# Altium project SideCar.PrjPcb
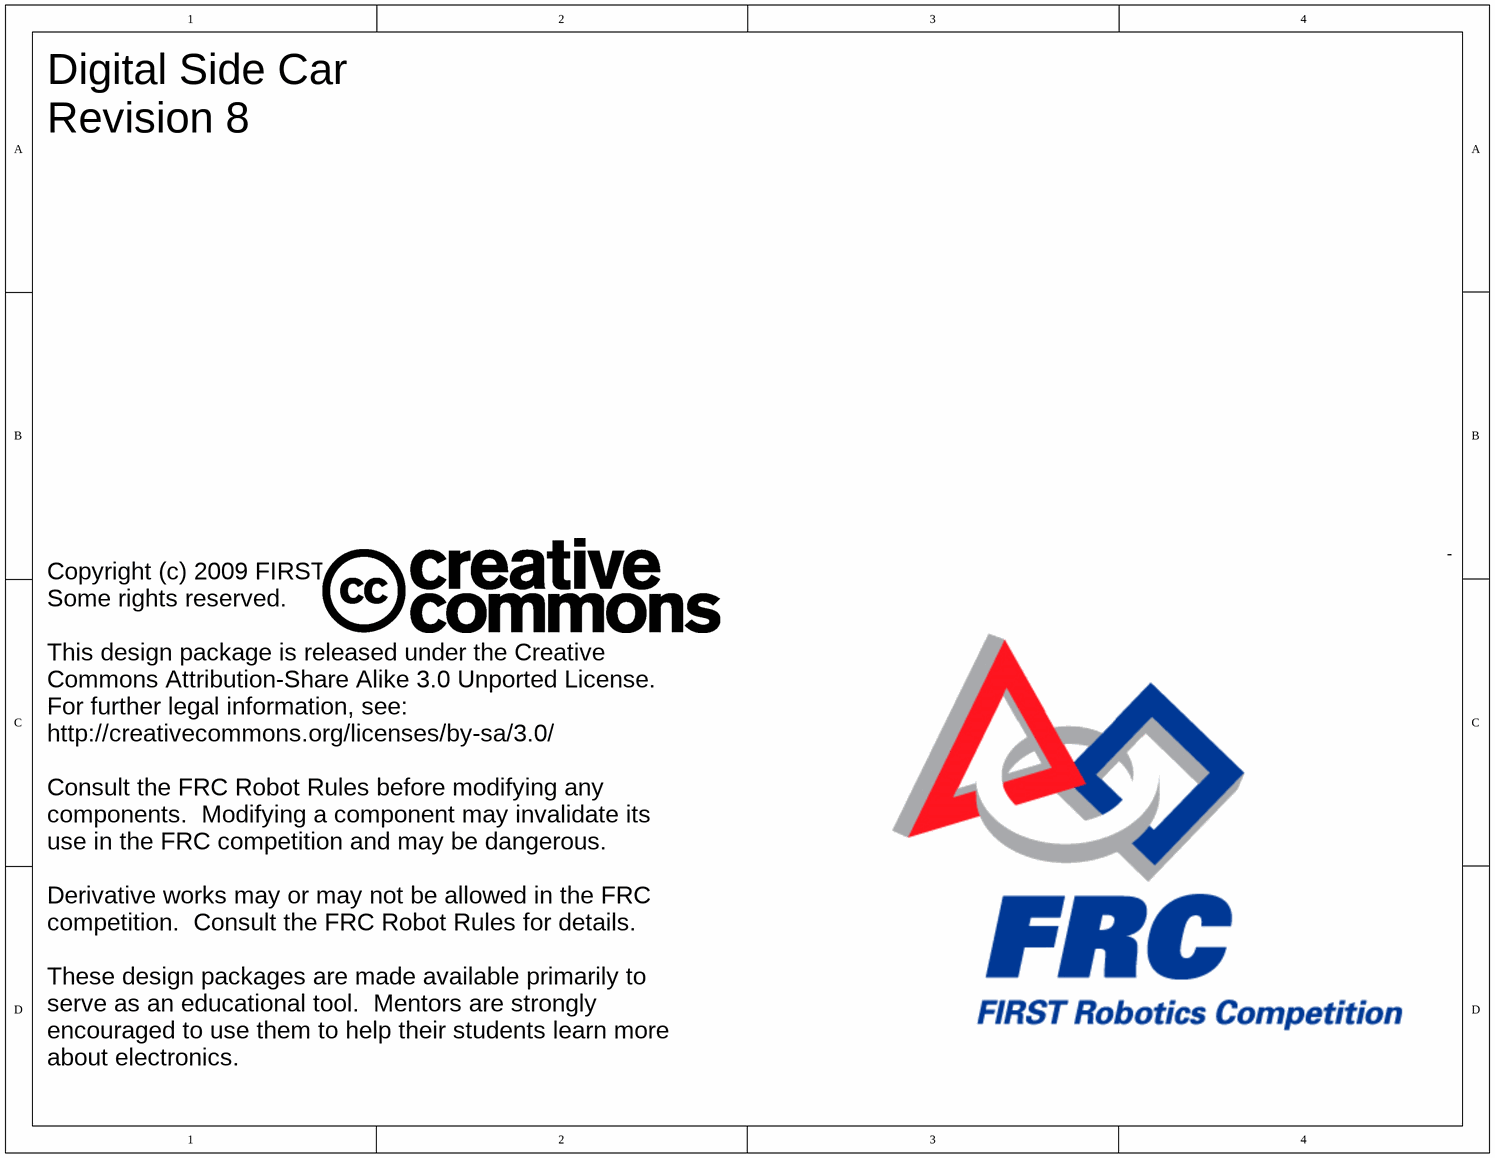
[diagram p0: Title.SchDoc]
ProjectTitle: Digital Side Car, Rev 8
5 sheets, 116 parts. Net scope: global (net labels, ports and power ports of the same name join across sheets).
Board file: SideCar.PcbDoc
Sheets:
  Title.SchDoc
  cRIO Connectors.SchDoc
  PWM Outputs.SchDoc
  Power.SchDoc
  Relay Outputs.SchDoc

## Sheet Title.SchDoc
size Letter; SheetNumber: 1

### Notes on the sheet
- Digital Side Car
  Revision 8
- Copyright (c) 2009 FIRST
  Some rights reserved.
  This design package is released under the Creative Commons Attribution-Share Alike 3.0 Unported License.  For further legal information, see:
  http://creativecommons.org/licenses/by-sa/3.0/
  Consult the FRC Robot Rules before modifying any components.  Modifying a component may invalidate its use in the FRC competition and may be dangerous.
  Derivative works may or may not be allowed in the FRC competition.  Consult the FRC Robot Rules for details.
  These design packages are made available primarily to serve as an educational tool.  Mentors are strongly encouraged to use them to help their students learn more about electronics.

## Sheet cRIO Connectors.SchDoc: cRIO Connectors
size Letter; DrawnBy: RHB; DocumentNumber: 1; Revision: 2; SheetNumber: 1; SheetTotal: 4
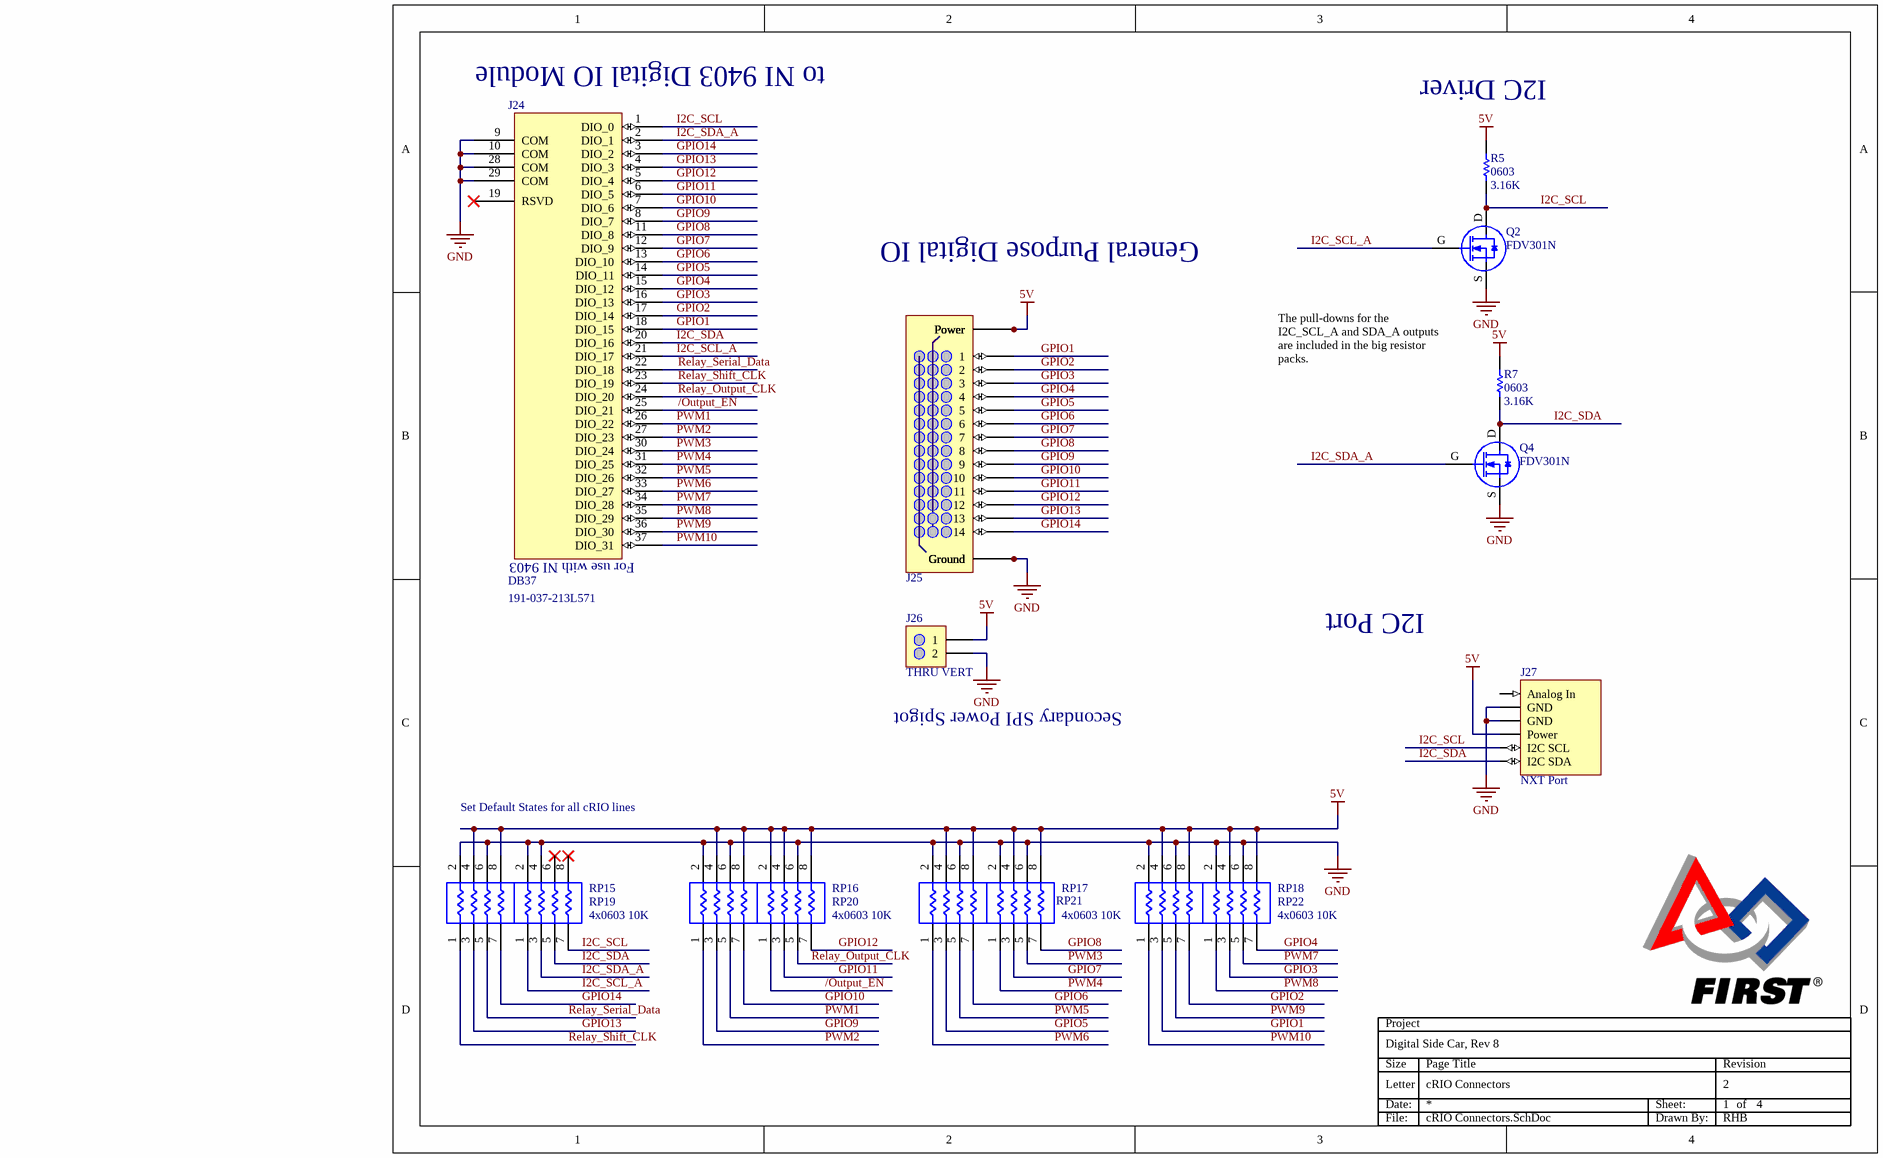
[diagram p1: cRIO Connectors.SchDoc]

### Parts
J24  DB37  MFG_PN: 191-037-213L571  [DB37- THRU]
J25  3x12 Bird Pins  [H100P3x14 TSW-114-07-T-T]  (value not drawn)
J26  THRU VERT  [H100P2]
J27  NXT Port  [NXT RJ]
Q2  FDV301N  [SOT-23 FET]
Q4  FDV301N  [SOT-23 FET]
R5  value 3.16K  Footprint: 0603  [R0603_C]  (hidden comment: 3.16k ohm 0603 1%)
R7  value 3.16K  Footprint: 0603  [R0603_C]  (hidden comment: 3.16k ohm 0603 1%)
RP15  4x0603 10K  [R0603x4 - Convex]
RP16  4x0603 10K  [R0603x4 - Convex]
RP17  4x0603 10K  [R0603x4 - Convex]
RP18  4x0603 10K  [R0603x4 - Convex]
RP19  4x0603 10K  [R0603x4 - Convex]  (value not drawn)
RP20  4x0603 10K  [R0603x4 - Convex]  (value not drawn)
RP21  4x0603 10K  [R0603x4 - Convex]  (value not drawn)
RP22  4x0603 10K  [R0603x4 - Convex]  (value not drawn)

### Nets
5V: J25.2(Power) J25.5(Power) J25.8(Power) J25.11(Power) J25.14(Power) J25.17(Power) J25.20(Power) J25.23(Power) J25.26(Power) J25.29(Power) J25.32(Power) J25.35(Power) J25.38(Power) J25.41(Power) J26.1 J27.4(Power) R5.2 R7.2 RP15.4 RP15.8 RP16.4 RP16.8 RP17.4 RP17.8 RP18.4 RP18.8 RP20.2 RP20.4 RP20.8 RP21.4 RP21.8 RP22.4 RP22.8
GND: J24.9(COM) J24.10(COM) J24.28(COM) J24.29(COM) J25.3(Ground) J25.6(Ground) J25.9(Ground) J25.12(Ground) J25.15(Ground) J25.18(Ground) J25.21(Ground) J25.24(Ground) J25.27(Ground) J25.30(Ground) J25.33(Ground) J25.36(Ground) J25.39(Ground) J25.42(Ground) J26.2 J27.2(GND) J27.3(GND) Q2.S Q4.S RP15.2 RP15.6 RP16.2 RP16.6 RP17.2 RP17.6 RP18.2 RP18.6 RP19.2 RP19.4 RP20.6 RP21.2 RP21.6 RP22.2 RP22.6
/Output_EN: J24.25(DIO_21) RP20.1
GPIO1: J24.18(DIO_15) J25.1 RP18.3
GPIO2: J24.17(DIO_14) J25.4(2) RP18.7
GPIO3: J24.16(DIO_13) J25.7(3) RP22.3
GPIO4: J24.15(DIO_12) J25.10(4) RP22.7
GPIO5: J24.14(DIO_11) J25.13(5) RP17.3
GPIO6: J24.13(DIO_10) J25.16(6) RP17.7
GPIO7: J24.12(DIO_9) J25.19(7) RP21.3
GPIO8: J24.11(DIO_8) J25.22(8) RP21.7
GPIO9: J24.8(DIO_7) J25.25(9) RP16.3
GPIO10: J24.7(DIO_6) J25.28(10) RP16.7
GPIO11: J24.6(DIO_5) J25.31(11) RP20.3
GPIO12: J24.5(DIO_4) J25.34(12) RP20.7
GPIO13: J24.4(DIO_3) J25.37(13) RP15.3
GPIO14: J24.3(DIO_2) J25.40(14) RP15.7
I2C_SCL: J24.1(DIO_0) J27.5(I2C_SCL) Q2.D R5.1 RP19.7
I2C_SCL_A: J24.21(DIO_17) Q2.G RP19.1
I2C_SDA: J24.20(DIO_16) J27.6(I2C_SDA) Q4.D R7.1 RP19.5
I2C_SDA_A: J24.2(DIO_1) Q4.G RP19.3
PWM1: J24.26(DIO_22) RP16.5
PWM2: J24.27(DIO_23) RP16.1
PWM3: J24.30(DIO_24) RP21.5
PWM4: J24.31(DIO_25) RP21.1
PWM5: J24.32(DIO_26) RP17.5
PWM6: J24.33(DIO_27) RP17.1
PWM7: J24.34(DIO_28) RP22.5
PWM8: J24.35(DIO_29) RP22.1
PWM9: J24.36(DIO_30) RP18.5
PWM10: J24.37(DIO_31) RP18.1
Relay_Output_CLK: J24.24(DIO_20) RP20.5
Relay_Serial_Data: J24.22(DIO_18) RP15.5
Relay_Shift_CLK: J24.23(DIO_19) RP15.1

Not connected (* = marked no-connect by the designer): J24 19(RSVD)*; J27 1(Analog_In); RP19 6* 8*

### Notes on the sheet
- (near J24) to NI 9403 Digital IO Module
- (near R5) I2C Driver
- General Purpose Digital IO
- The pull-downs for the I2C_SCL_A and SDA_A outputs are included in the big resistor packs.
- I2C Port
- Secondary SPI Power Spigot
- Set Default States for all cRIO lines

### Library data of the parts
J24 = Norcomp 191-037-213L571: D-SUB RCPT STR 37POS PCB AU; DIST: DigiKey; DIST_PN: 191-037-213L571-ND; MFG: Norcomp Inc.; Cost (MOQ): 3.00900
J25 = H100 3x14 THRU VERT: 3x14 Bird Pins; DIST: Samtec; DIST_PN: TSW-114-07-T-T
J26 = H100 1x2 THRU VERT: 1x2 Bird Pins; DIST: Samtec; DIST_PN: TSW-102-07-T-S; BOM Note: Generic
J27 = NXT RJ12 Connector
Q2 Q4 = FDV301N: N-Ch Logic FET, 25V, 0.22A, 5 Ohm; MFG: Fairchild; DIST: DigiKey; DIST_PN: FDV301NCT-ND; R_DS: 4000; V_DS: 25; V_GS: 8; R?JC: 357; Topology: N; Cost (1000): 0.05720; Cost (MOQ): 026000; Q_G (nC): 0.49; V_THRESH (Volts): 0.65 - 0.85 - 1.5; ID @ TA = 25°C (Amps): 0.22
R5 R7 = 3.16k ohm 0603 1%: MFG: Rohm; MFG_PN: MCR03EZPFX3161; DIST: DigiKey; DIST_PN: RHM3.16KHCT-ND; Power: 0.1 W
RP15-RP18 = 10k 5% 4x0603 Isolated: 10K 5% Isolated Resistor Network; MFG: Yageo; MFG_PN: YC164-JR-0710KL; DIST: DigiKey; DIST_PN: YC164J-10KCT-ND; Number of Resistors: 4; Power: 62.5mW; Cost (1000): 0.00630; Cost (MOQ): 0.01100
RP19-RP22 = 10K 5% 4x0603 Isolated: 10K 5% Isolated Resistor Network; MFG: Yageo; MFG_PN: YC164-JR-0710KL; DIST: DigiKey; DIST_PN: YC164J-10KCT-ND; Number of Resistors: 4; Power: 62.5mW; Cost (1000): 0.00630; Cost (MOQ): 0.01100

## Sheet PWM Outputs.SchDoc: PWM Outputs
size Letter; DrawnBy: RHB; DocumentNumber: 3; Revision: 4; SheetNumber: 2; SheetTotal: 4
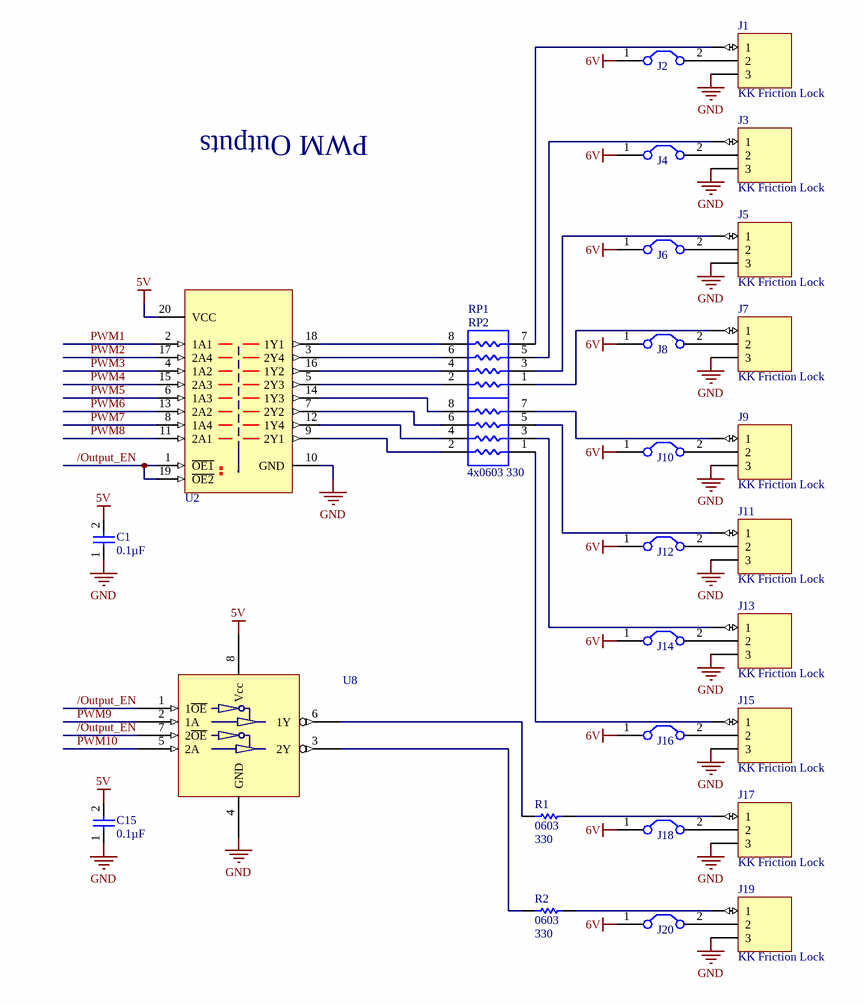
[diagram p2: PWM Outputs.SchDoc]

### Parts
(Parts that share a designator on the sheet are numbered #1, #2 ... from top to bottom, then left to right.)
C1  value 0.1µF  [C0805_C]  (hidden comment: 0.1uF 0805 Bypass)
C15  value 0.1µF  [C0805_C]  (hidden comment: 0.1uF 0805 Bypass)
J1  KK Friction Lock  [KK100P3]
J2  Jumper  [H100P2]  (value not drawn)
J3  KK Friction Lock  [KK100P3]
J4  Jumper  [H100P2]  (value not drawn)
J5  KK Friction Lock  [KK100P3]
J6  Jumper  [H100P2]  (value not drawn)
J7  KK Friction Lock  [KK100P3]
J8  Jumper  [H100P2]  (value not drawn)
J9  KK Friction Lock  [KK100P3]
J10  Jumper  [H100P2]  (value not drawn)
J11  KK Friction Lock  [KK100P3]
J12  Jumper  [H100P2]  (value not drawn)
J13  KK Friction Lock  [KK100P3]
J14  Jumper  [H100P2]  (value not drawn)
J15  KK Friction Lock  [KK100P3]
J16  Jumper  [H100P2]  (value not drawn)
J17  KK Friction Lock  [KK100P3]
J18  Jumper  [H100P2]  (value not drawn)
J19  KK Friction Lock  [KK100P3]
J20  Jumper  [H100P2]  (value not drawn)
R1  value 330  Footprint: 0603  [R0603_C]  (hidden comment: 470 ohm 0603 1%)
R2  value 330  Footprint: 0603  [R0603_C]  (hidden comment: 470 ohm 0603 1%)
RP1  4x0603 330  [R0603x4 - Convex]
RP2  4x0603 330  [R0603x4 - Convex]  (value not drawn)
U2#1  SN74AC244DWR  [DW020_N]  (value not drawn)
U8  Dual Buffer  [TSOP65P400X130-8N]  (value not drawn)

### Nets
5V: C1.2 C15.2 U2#1.20(VCC) U8.8(Vcc)
6V: J2.1 J4.1 J6.1 J8.1 J10.1 J12.1 J14.1 J16.1 J18.1 J20.1
GND: C1.1 C15.1 J1.3 J3.3 J5.3 J7.3 J9.3 J11.3 J13.3 J15.3 J17.3 J19.3 U2#1.10(GND) U8.4(GND)
/Output_EN: U2#1.1(~{OE1}) U2#1.19(~{OE2}) U8.1(1~{OE}) U8.7(2~{OE})
PWM1: U2#1.2(1A1)
PWM2: U2#1.17(2A4)
PWM3: U2#1.4(1A2)
PWM4: U2#1.15(2A3)
PWM5: U2#1.6(1A3)
PWM6: U2#1.13(2A2)
PWM7: U2#1.8(1A4)
PWM8: U2#1.11(2A1)
PWM9: U8.2(1A)
PWM10: U8.5(2A)
NetJ1_1: J1.1 RP2.7
NetJ1_2: J1.2 J2.2
NetJ3_1: J3.1 RP2.5
NetJ3_2: J3.2 J4.2
NetJ5_1: J5.1 RP2.3
NetJ5_2: J5.2 J6.2
NetJ7_1: J7.1 RP2.1
NetJ7_2: J7.2 J8.2
NetJ9_1: J9.1 RP1.7
NetJ9_2: J9.2 J10.2
NetJ11_1: J11.1 RP1.5
NetJ11_2: J11.2 J12.2
NetJ13_1: J13.1 RP1.3
NetJ13_2: J13.2 J14.2
NetJ15_1: J15.1 RP1.1
NetJ15_2: J15.2 J16.2
NetJ17_1: J17.1 R1.1
NetJ17_2: J17.2 J18.2
NetJ19_1: J19.1 R2.1
NetJ19_2: J19.2 J20.2
NetR1_2: R1.2 U8.6(1Y)
NetR2_2: R2.2 U8.3(2Y)
NetRP1_2: RP1.2 U2#1.9(2Y1)
NetRP1_4: RP1.4 U2#1.12(1Y4)
NetRP1_6: RP1.6 U2#1.7(2Y2)
NetRP1_8: RP1.8 U2#1.14(1Y3)
NetRP2_2: RP2.2 U2#1.5(2Y3)
NetRP2_4: RP2.4 U2#1.16(1Y2)
NetRP2_6: RP2.6 U2#1.3(2Y4)
NetRP2_8: RP2.8 U2#1.18(1Y1)

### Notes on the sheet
- PWM Outputs

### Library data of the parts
C1 C15 = 0.1uF 0805 Bypass: Capacitor; MFG: Kemet; MFG_PN: C0805C104K5RACTU; DIST: DigiKey; DIST_PN: 399-1170-1-ND; Tolerance: ±10%; Temperature Coefficient: X7R; Voltage: 50 V
J1 J3 J5 J7 J9 J11 J13 J15 J17 J19 = KK100P3: DIST: DigiKey; DIST_PN: WM4201-ND; MFG: Molex/Waldom Electronics Corp; Checked: SCH 11/11/07
J2 J4 J6 J8 J10 J12 J14 J16 J18 J20 = Jumper 100mil: DIST: DigiKey; DIST_PN: WM4000-ND; MFG: Molex/Waldom Electronics Corp; Checked: SCH 11/17/07
R1 R2 = 330 ohm 0603 1%: MFG: Rohm; MFG_PN: MCR03EZPFX3300; DIST: DigiKey; DIST_PN: RHM330HCT-ND; Power: 0.1; Cost (1000): 0.01595; Cost (MOQ): 0.076; BOM Note: Generic - May be replaced by equal or better part
RP1 RP2 = 330 5% 4x0603 Isolated: 330 5% Isolated Resistor Network; MFG: Yageo; MFG_PN: YC164-JR-07330RL; DIST: DigiKey; DIST_PN: YC164J-330CT-ND; Number of Resistors: 4; Power: 62.5mW; Value: 330; Cost (1000): 0.00630; Cost (MOQ): 0.01100
U2#1 = SN74AC244DWR: 8x Line Driver, Non-Inverting; MFG: TI; DIST: DigiKey; DIST_PN: 296-1057-1-ND; Cost (1000): 0.18260; Cost (MOQ): 0.55000
U8 = SN74LVC2G125DCTR Dual Buffer: MFG: TI; DIST: DigiKey; DIST_PN: 296-12164-1-ND; Output Current: 32mA @ Vcc 4.5; Operating Voltage: 1.65 to 5.5 V; Cost (1000): 0.15960; Cost (MOQ): 0.48000

## Sheet Power.SchDoc: Power Input, Supplies & Indicators
size Letter; DrawnBy: EJVW; Revision: 4; SheetNumber: 3; SheetTotal: 4
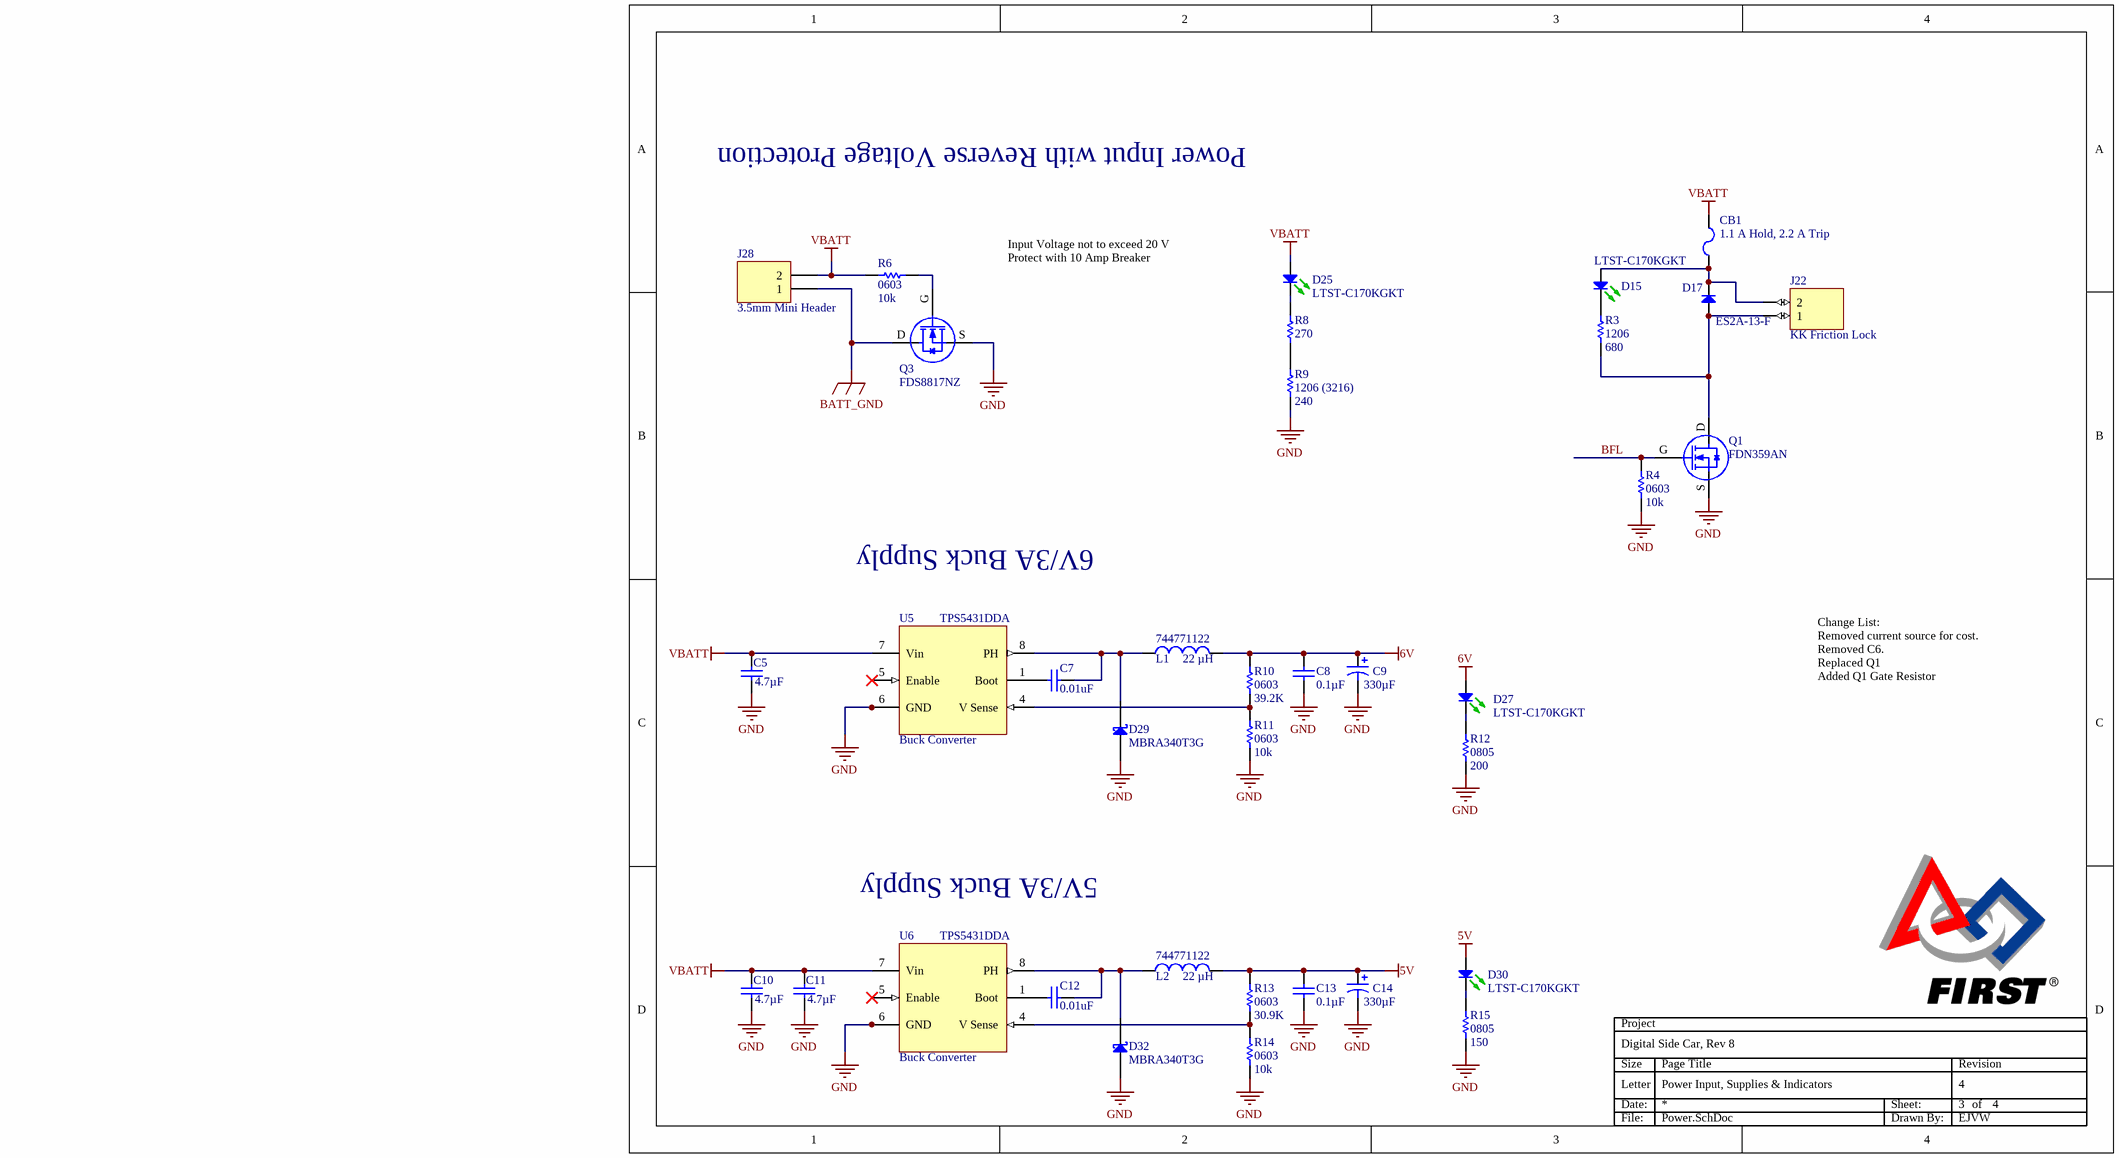
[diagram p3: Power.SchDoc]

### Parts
C5  value 4.7µF  [C0805_C]  (hidden comment: 4.7UF 0805 25V X5R)
C7  value 0.01uF  [C0603_C]  (hidden comment: 0.01uF 0603)
C8  value 0.1µF  [C0805_C]  (hidden comment: 0.1uF 0805 Bypass)
C9  value 330µF  [SMT-CAN Nippon F80]  (hidden comment: 330µF SMT - Chemi-Con)
C10  value 4.7µF  [C0805_C]  (hidden comment: 4.7UF 0805 25V X5R)
C11  value 4.7µF  [C0805_C]  (hidden comment: 4.7UF 0805 25V X5R)
C12  value 0.01uF  [C0603_C]  (hidden comment: 0.01uF 0603)
C13  value 0.1µF  [C0805_C]  (hidden comment: 0.1uF 0805 Bypass)
C14  value 330µF  [SMT-CAN Nippon F80]  (hidden comment: 330µF SMT - Chemi-Con)
CB1  1.1 A Hold, 2.2 A Trip  [PTC1812]
D15  LTST-C170KGKT  [LED_0805 1.1 Green]
D17  25ns 2A Standard Rectifier  [SMB]  (value not drawn)
D25  LTST-C170KGKT  [LED_0805 1.1 Green]
D27  LTST-C170KGKT  [LED_0805 1.1 Green]
D29  MBRA340T3G  [SMA]
D30  LTST-C170KGKT  [LED_0805 1.1 Green]
D32  MBRA340T3G  [SMA]
J22  KK Friction Lock  [KK100P2]
J28  3.5mm Mini Header  [WAGO 734-132]
L1  value 22 µH  MFG_PN: 744771122  [Wurth WE-PD L]  (hidden comment: 22 µH 3.37 A)
L2  value 22 µH  MFG_PN: 744771122  [Wurth WE-PD L]  (hidden comment: 22 µH 3.37 A)
Q1  FDN359AN  [SOT-23 FET]
Q3  FDS8817NZ  [SO-8_M FET]
R3  value 680  Footprint: 1206  [R1206_C]  (hidden comment: 680 ohm 1206 5%)
R4  value 10k  Footprint: 0603  [R0603_C]  (hidden comment: 10k ohm 0603 1%)
R6  value 10k  Footprint: 0603  [R0603_C]  (hidden comment: 10k ohm 0603 1%)
R8  value 270  [R1206_C]  (hidden comment: 270 ohm 1206 5%)
R9  value 240  Footprint: 1206 (3216)  [R1206_C]  (hidden comment: 240 ohm 1206 5%)
R10  value 39.2K  Footprint: 0603  [R0603_C]  (hidden comment: 2.55k ohm 0603 1%)
R11  value 10k  Footprint: 0603  [R0603_C]  (hidden comment: 10k ohm 0603 1%)
R12  value 200  Footprint: 0805  [R0805_M]  (hidden comment: 200 ohm 0805 1%)
R13  value 30.9K  Footprint: 0603  [R0603_C]  (hidden comment: 30.9k ohm 0603 1%)
R14  value 10k  Footprint: 0603  [R0603_C]  (hidden comment: 10k ohm 0603 1%)
R15  value 150  Footprint: 0805  [R0805_M]  (hidden comment: 150 ohm 0805 1%)
U5  Buck Converter  MFG_PN: TPS5431DDA  [TPS543X]
U6  Buck Converter  MFG_PN: TPS5431DDA  [TPS543X]

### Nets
5V: C13.2 C14.+ D30.A L2.2 R13.2
6V: C8.2 C9.+ D27.A L1.2 R10.2
BATT_GND: J28.1 Q3.D
GND: C5.1 C8.1 C9.- C10.1 C11.1 C13.1 C14.- D29.A D32.A Q1.S Q3.S R4.1 R9.1 R11.1 R12.1 R14.1 R15.1 U5.6(GND) U5.PAD U6.6(GND) U6.PAD
VBATT: C5.2 C10.2 C11.2 CB1.2 D25.A J28.2 R6.2 U5.7(Vin) U6.7(Vin)
BFL: Q1.G R4.2
NetC7_1: C7.1 U5.1(Boot)
NetC7_2: C7.2 D29.K L1.1 U5.8(PH)
NetC12_1: C12.1 U6.1(Boot)
NetC12_2: C12.2 D32.K L2.1 U6.8(PH)
NetCB1_1: CB1.1 D15.A D17.K J22.2
NetD15_K: D15.K R3.2
NetD17_A: D17.A J22.1 Q1.D R3.1
NetD25_K: D25.K R8.2
NetD27_K: D27.K R12.2
NetD30_K: D30.K R15.2
NetQ3_G: Q3.G R6.1
NetR8_1: R8.1 R9.2
NetR10_1: R10.1 R11.2 U5.4(V_Sense)
NetR13_1: R13.1 R14.2 U6.4(V_Sense)

Not connected (* = marked no-connect by the designer): U5 5(Enable)*; U6 5(Enable)*

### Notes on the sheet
- Power Input with Reverse Voltage Protection
- Input Voltage not to exceed 20 V
  Protect with 10 Amp Breaker
- 6V/3A Buck Supply
- Change List:
  Removed current source for cost.
  Removed C6.
  Replaced Q1
  Added Q1 Gate Resistor
- 5V/3A Buck Supply

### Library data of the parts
C5 C10 C11 = 4.7uF 0805 25V X5R: CERAMIC 4.7uF 25V X5R 0805; MFG: Panasonic - ECG; MFG_PN: ECJ-2FB1E475M; DIST: DigiKey; DIST_PN: PCC2321CT-ND; Tolerance: ±20%; Cost (1000): 0.08988
C7 C12 = 0.01 uF 0603 50V: MFG: Kemet; MFG_PN: C0603C103K5RACTU; DIST: DigiKey; DIST_PN: 399-1091-1-ND; Tolerance: ±10%; Temperature Coefficient: X7R; Voltage: 50V
C8 C13 = 0.1uF 0805 Bypass: Capacitor; MFG: Kemet; MFG_PN: C0805C104K5RACTU; DIST: DigiKey; DIST_PN: 399-1170-1-ND; Tolerance: ±10%; Temperature Coefficient: X7R; Voltage: 50 V; Cost (1000): 0.01260
C9 C14 = 330µF 6.3V CAN-SMT: 330µF 6.3V ELECT CAN-SMT; DIST: DigiKey; DIST_PN: 565-2059-1-ND; MFG: United Chemi-Con; MFG_PN: EMVA6R3ADA331MF80G; Tolerance: ±20%; Max Temperature: 85 C; Ripple Current: 0.135 A; Cost (1000): 0.10266
CB1 = MF-MSMF110/16-2: PTC 1.1A /  2.2A SMT; MFG: Bourns Inc.; DIST: DigiKey; DIST_PN: MF-MSMF110/16-2CT-ND; R_min: 0.04; R_max: 0.21; Time to Trip: 0.3 s @ 8 A; V Max: 16V; I trip (A): 2.2; I max (A): 100A; Cost (1000): 0.42300; Cost (MOQ): 0.63000
D15 = LTST-C170KGKT: Green 0805 20mA 2.0V 35mCd; MFG: LITE-ON INC; DIST: DigiKey; DIST_PN: 160-1414-1-ND; I_F: 20; Luminous Intensity: 35; Maximum Continuous Current: 30; V_F: 2.0; Cost (1000): 0.05800; Cost (MOQ): 0.12000
D17 = ES2A-13-F: MFG: Diodes Inc; DIST: DIGIKEY; DIST_PN: ES2A-FDICT-ND; Voltage Rating: 50 V; Surge Rating (8.3ms Half Sine): 50 A; Forward Voltage: 0.92 V
D25 D27 D30 = LTST-C170KGKT: Green 0805 20mA 2.0V 35mCd; DIST: DigiKey; DIST_PN: 160-1414-1-ND; MFG: LITE-ON INC; V_F: 2.0; I_F: 20; Maximum Continuous Current: 30; Luminous Intensity: 35; Cost (1000): 0.05800; Cost (MOQ): 0.12000
D29 D32 = MBRA340T3G: 3A Schottky Diode; DIST: DigiKey; DIST_PN: MBRA340T3GOSCT-ND; MFG: ON Semiconductor; Forward Voltage: 0.38; Surge Rating (8.3ms Half Sine): 100A; Voltage Rating: 40V
J22 = KK100P2: DIST: DigiKey; DIST_PN: WM4200-ND; MFG: Molex/Waldom Electronics Corp; Checked: SCH 11/11/07
J28 = WAGO 734-132: 3.5mm Header Protected against Mismating; MFG: WAGO; Current Rating: 10 A; Mates With: 734-102/037-000
L1 L2 = WE-PD-L 22: 22 µH 3.37 A 20% SMD; MFG: Wurth; DIST: Digikey; DIST_PN: 732-1211-2-ND; DCR (Ohms): .0648; Cost (1000): 1.02000; Cost (MOQ): 3.06000; IRMS (40C) A: 3.37; ISAT (10%)  A: 3.77; SRF (MHz): 13
Q1 = FDN359AN: N-Channel Powertrench MOSFET, 30V, 2.7A, 2.5mOhm; MFG: Fairchild; DIST: DigiKey; DIST_PN: FDN359ANCT-ND; R_DS: 46 mOhms; V_GS: 20V; I_D Continuous: 2.7; Checked: SCH 11/17/07; R?JC: 250 C/W; Topology: N; Cost (1000): 0.19551; Cost (MOQ): 0.59000; Q_G (nC): 5; V_THRESH (Volts): 1 - 1.6 - 3
Q3 = FDS8817NZ: N-CH 30V 8SOIC, ESD Protected; MFG: Fairchild Semiconductor; DIST: DigiKey; DIST_PN: FDS8817NZCT-ND; R_DS: 5.4mOhms; V_DS: 30; V_GS: 20; R?JC: 25; Topology: N; Q_G (nC): 45; V_THRESH (Volts): 1.0 - 1.8 - 3.0; Cost (1000): 0.34913; Cost (MOQ): 0.79; I_D Continuous: 15
R3 = 680 ohm 1206 5%: MFG: Rohm; MFG_PN: MCR18EZPJ681; DIST: DigiKey; DIST_PN: RHM680ERCT-ND; Power: 0.25; Cost (1000): 0.01929; Cost (MOQ): 0.04000
R4 R6 R11 R14 = 10k ohm 0603 1%: MFG: Rohm; MFG_PN: MCR03EZPFX1002; DIST: DigiKey; DIST_PN: RHM10.0KHCT-ND; Power: 0.1 W
R8 = 270 ohm 1206 5%: MFG: Rohm; MFG_PN: MCR18EZPJ271; DIST: DigiKey; DIST_PN: RHM270ERCT-ND; Power: 0.25W, 1/4W; Cost (1000): 0.01929
R9 = 240 ohm 1206 5%: MFG: Rohm; MFG_PN: MCR18EZPJ241; DIST: DigiKey; DIST_PN: RHM240ERCT-ND; Power: 0.25W, 1/4W; Cost (1000): 0.01929
R10 = 39.2k ohm 0603 1%: MFG: Rohm; MFG_PN: MCR03EZPFX3922; DIST: DigiKey; DIST_PN: RHM39.2KHCT-ND; Power: 0.1 W; Cost (1000): 0.01595; Cost (MOQ): 0.07600
R12 = 200 ohm 0805 1%: MFG: Rohm; MFG_PN: MCR10EZPF2000; DIST: DigiKey; DIST_PN: RHM200CRCT-ND; Power: 0.125W, 1/8W; Cost (1000): 0.01795; Cost (MOQ): 0.03700; BOM Note: Generic
R13 = 30.9k ohm 0603 1%: MFG: Rohm; MFG_PN: MCR03EZPFX3092; DIST: DigiKey; DIST_PN: RHM30.9KHCT-ND; Power: 0.1 W; Cost (1000): 0.01595; Cost (MOQ): 0.07600
R15 = 150 ohm 0805 1%: MFG: Rohm; MFG_PN: MCR10EZPF1500; DIST: DigiKey; DIST_PN: RHM150CRCT-ND; Power: 0.125W, 1/8W; Cost (1000): 0.01795; Cost (MOQ): 0.03700; BOM Note: Generic
U5 U6 = TPS5431: 3-A, WIDE INPUT RANGE, STEP-DOWN SWIFT CONVERTER; ADJ Pin Voltage: 1.221; Current Limit: 3; DIST: DigiKey; DIST_PN: 296-19662-5-ND; Max Voltage: 23; MFG: TI; Quiescent Current: 3 mA; Shutdown Current: 20 uA; Voltage Output: 1.22 +; Switch Frequency (kHz): 500; Cost (1000): 2.20

## Sheet Relay Outputs.SchDoc: Relay Outputs
size Letter; DrawnBy: RHB; DocumentNumber: 4; Revision: 4; SheetNumber: 4; SheetTotal: 4
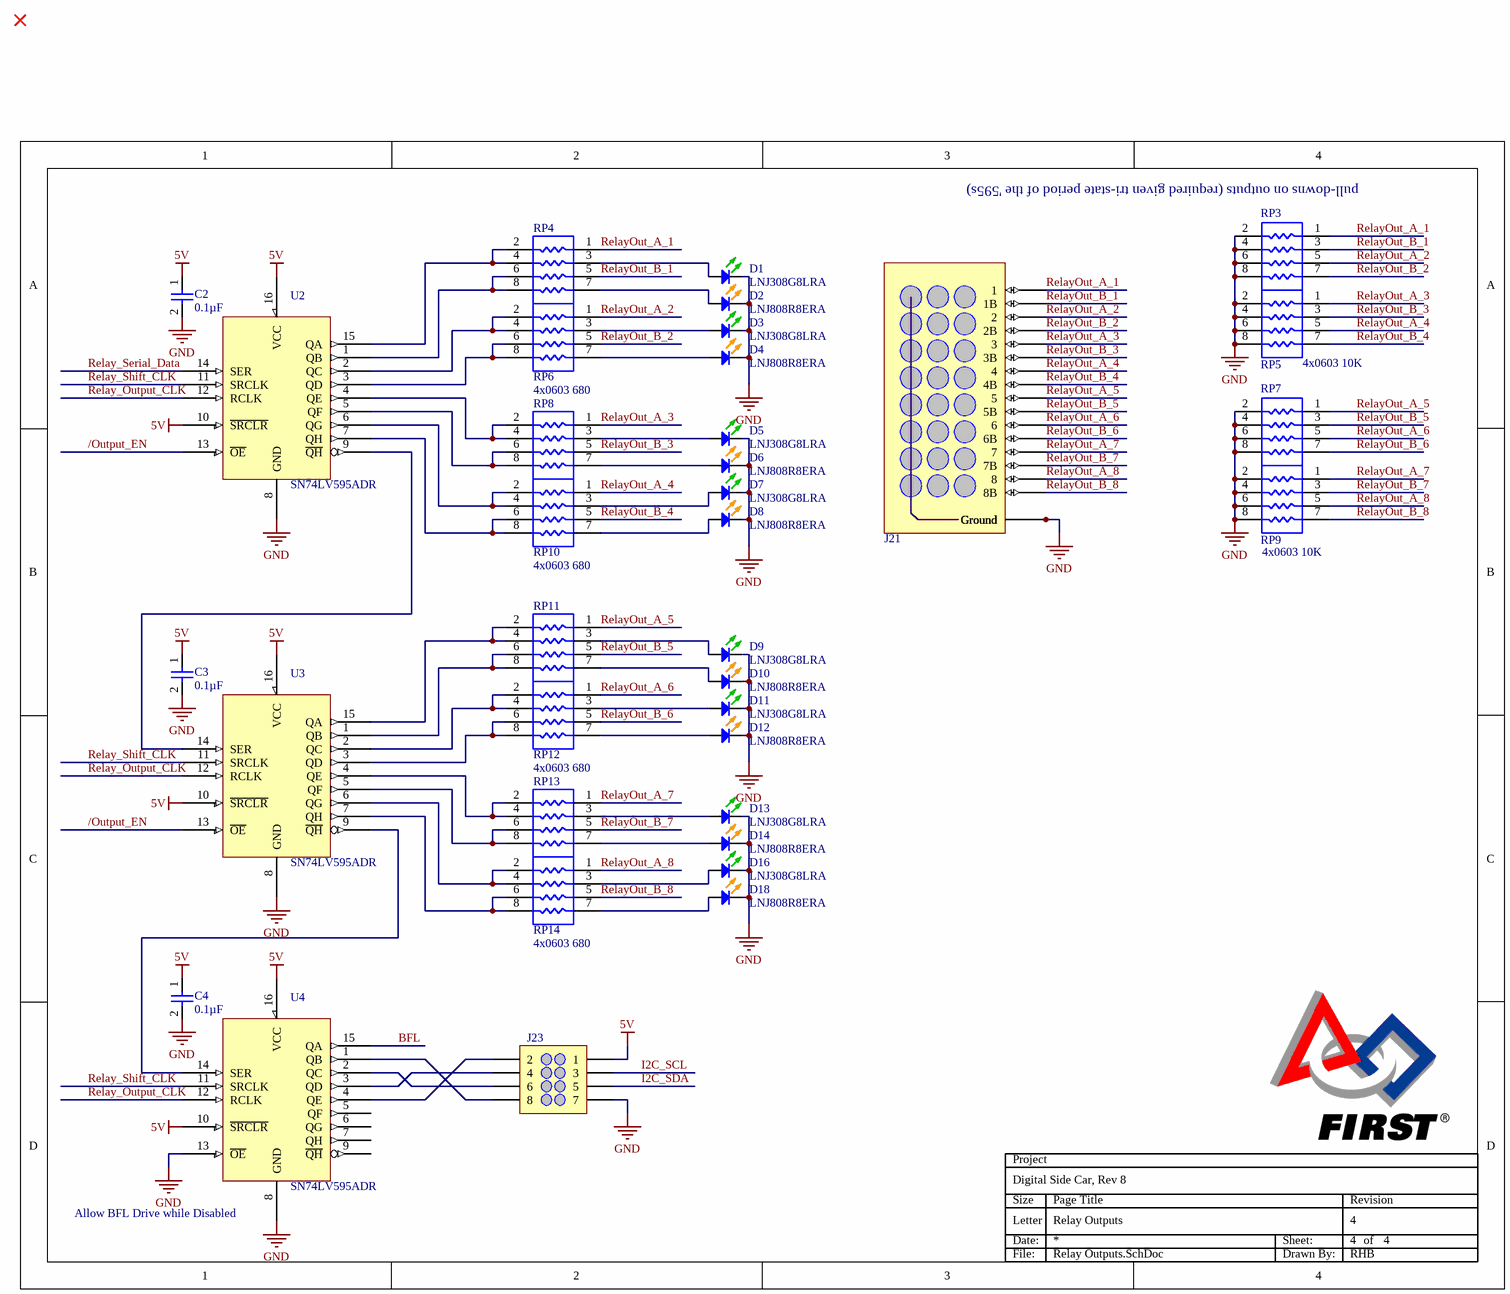
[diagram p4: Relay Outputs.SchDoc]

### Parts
(Parts that share a designator on the sheet are numbered #1, #2 ... from top to bottom, then left to right.)
C2  value 0.1µF  [C0805_C]  (hidden comment: 0.1uF 0805 Bypass)
C3  value 0.1µF  [C0805_C]  (hidden comment: 0.1uF 0805 Bypass)
C4  value 0.1µF  [C0805_C]  (hidden comment: 0.1uF 0805 Bypass)
D1  LNJ308G8LRA  [LED_0603 0.8 Green]
D2  LNJ808R8ERA  [LED_0603 0.8Orange]
D3  LNJ308G8LRA  [LED_0603 0.8 Green]
D4  LNJ808R8ERA  [LED_0603 0.8Orange]
D5  LNJ308G8LRA  [LED_0603 0.8 Green]
D6  LNJ808R8ERA  [LED_0603 0.8Orange]
D7  LNJ308G8LRA  [LED_0603 0.8 Green]
D8  LNJ808R8ERA  [LED_0603 0.8Orange]
D9  LNJ308G8LRA  [LED_0603 0.8 Green]
D10  LNJ808R8ERA  [LED_0603 0.8Orange]
D11  LNJ308G8LRA  [LED_0603 0.8 Green]
D12  LNJ808R8ERA  [LED_0603 0.8Orange]
D13  LNJ308G8LRA  [LED_0603 0.8 Green]
D14  LNJ808R8ERA  [LED_0603 0.8Orange]
D16  LNJ308G8LRA  [LED_0603 0.8 Green]
D18  LNJ808R8ERA  [LED_0603 0.8Orange]
J21  3x8 Bird Pins  [H100P3x8 TSW-108-07-T-T]  (value not drawn)
J23  THRU VERT  [H100P2x4 TSW-104-07-T-D]  (value not drawn)
RP3  4x0603 10K  [R0603x4 - Convex]
RP4  4x0603 680  [R0603x4 - Convex]
RP5  4x0603 10K  [R0603x4 - Convex]  (value not drawn)
RP6  4x0603 680  [R0603x4 - Convex]  (value not drawn)
RP7  4x0603 10K  [R0603x4 - Convex]
RP8  4x0603 680  [R0603x4 - Convex]
RP9  4x0603 10K  [R0603x4 - Convex]  (value not drawn)
RP10  4x0603 680  [R0603x4 - Convex]  (value not drawn)
RP11  4x0603 680  [R0603x4 - Convex]
RP12  4x0603 680  [R0603x4 - Convex]  (value not drawn)
RP13  4x0603 680  [R0603x4 - Convex]
RP14  4x0603 680  [R0603x4 - Convex]  (value not drawn)
U2#2  MFG_PN: SN74LV595ADR  [D016_L]  (hidden comment: SN74LV595ADR Shift Register)
U3  MFG_PN: SN74LV595ADR  [D016_L]  (hidden comment: SN74LV595ADR Shift Register)
U4  MFG_PN: SN74LV595ADR  [D016_L]  (hidden comment: SN74LV595ADR Shift Register)

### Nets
5V: C2.1 C3.1 C4.1 J23.1 U2#2.10(~{SRCLR}) U2#2.16(VCC) U3.10(~{SRCLR}) U3.16(VCC) U4.10(~{SRCLR}) U4.16(VCC)
GND: C2.2 C3.2 C4.2 D1.K D2.K D3.K D4.K D5.K D6.K D7.K D8.K D9.K D10.K D11.K D12.K D13.K D14.K D16.K D18.K J21.3(Ground) J21.6(Ground) J21.9(Ground) J21.12(Ground) J21.15(Ground) J21.18(Ground) J21.21(Ground) J21.24(Ground) J23.7 RP3.2 RP3.4 RP3.6 RP3.8 RP5.2 RP5.4 RP5.6 RP5.8 RP7.2 RP7.4 RP7.6 RP7.8 RP9.2 RP9.4 RP9.6 RP9.8 U2#2.8(GND) U3.8(GND) U4.8(GND) U4.13(~{OE})
/Output_EN: U2#2.13(~{OE}) U3.13(~{OE})
BFL: U4.15(QA)
I2C_SCL: J23.3
I2C_SDA: J23.5
Relay_Output_CLK: U2#2.12(RCLK) U3.12(RCLK) U4.12(RCLK)
Relay_Serial_Data: U2#2.14(SER)
Relay_Shift_CLK: U2#2.11(SRCLK) U3.11(SRCLK) U4.11(SRCLK)
RelayOut_A_1: J21.1 RP3.1 RP4.1
RelayOut_A_2: J21.4(2) RP3.5 RP6.1
RelayOut_A_3: J21.7(3) RP5.1 RP8.1
RelayOut_A_4: J21.10(4) RP5.5 RP10.1
RelayOut_A_5: J21.13(5) RP7.1 RP11.1
RelayOut_A_6: J21.16(6) RP7.5 RP12.1
RelayOut_A_7: J21.19(7) RP9.1 RP13.1
RelayOut_A_8: J21.22(8) RP9.5 RP14.1
RelayOut_B_1: J21.2(1B) RP3.3 RP4.5
RelayOut_B_2: J21.5(2B) RP3.7 RP6.5
RelayOut_B_3: J21.8(3B) RP5.3 RP8.5
RelayOut_B_4: J21.11(4B) RP5.7 RP10.5
RelayOut_B_5: J21.14(5B) RP7.3 RP11.5
RelayOut_B_6: J21.17(6B) RP7.7 RP12.5
RelayOut_B_7: J21.20(7B) RP9.3 RP13.5
RelayOut_B_8: J21.23(8B) RP9.7 RP14.5
NetD1_A: D1.A RP4.3
NetD2_A: D2.A RP4.7
NetD3_A: D3.A RP6.3
NetD4_A: D4.A RP6.7
NetD5_A: D5.A RP8.3
NetD6_A: D6.A RP8.7
NetD7_A: D7.A RP10.3
NetD8_A: D8.A RP10.7
NetD9_A: D9.A RP11.3
NetD10_A: D10.A RP11.7
NetD11_A: D11.A RP12.3
NetD12_A: D12.A RP12.7
NetD13_A: D13.A RP13.3
NetD14_A: D14.A RP13.7
NetD16_A: D16.A RP14.3
NetD18_A: D18.A RP14.7
NetJ23_2: J23.2 U4.4(QE)
NetJ23_4: J23.4 U4.3(QD)
NetJ23_6: J23.6 U4.2(QC)
NetJ23_8: J23.8 U4.1(QB)
NetRP4_2: RP4.2 RP4.4 U2#2.15(QA)
NetRP4_6: RP4.6 RP4.8 U2#2.1(QB)
NetRP6_2: RP6.2 RP6.4 U2#2.2(QC)
NetRP6_6: RP6.6 RP6.8 U2#2.3(QD)
NetRP8_2: RP8.2 RP8.4 U2#2.4(QE)
NetRP8_6: RP8.6 RP8.8 U2#2.5(QF)
NetRP10_2: RP10.2 RP10.4 U2#2.6(QG)
NetRP10_6: RP10.6 RP10.8 U2#2.7(QH)
NetRP11_2: RP11.2 RP11.4 U3.15(QA)
NetRP11_6: RP11.6 RP11.8 U3.1(QB)
NetRP12_2: RP12.2 RP12.4 U3.2(QC)
NetRP12_6: RP12.6 RP12.8 U3.3(QD)
NetRP13_2: RP13.2 RP13.4 U3.4(QE)
NetRP13_6: RP13.6 RP13.8 U3.5(QF)
NetRP14_2: RP14.2 RP14.4 U3.6(QG)
NetRP14_6: RP14.6 RP14.8 U3.7(QH)
NetU2#2_9: U2#2.9(~{QH}) U3.14(SER)
NetU3_9: U3.9(~{QH}) U4.14(SER)

Not connected (* = marked no-connect by the designer): U4 5(QF) 6(QG) 7(QH) 9(~{QH})

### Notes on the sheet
- (near RP3) pull-downs on outputs (required given tri-state period of the '595s)
- (near U4) Allow BFL Drive while Disabled

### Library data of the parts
C2-C4 = 0.1uF 0805 Bypass: as C1 on sheet PWM Outputs
D1 D3 D5 D7 D9 D11 D13 D16 = LNJ308G8LRA: Green 0603 5mA 1.9V 3mCd; MFG: Panasonic - SSG; DIST: DigiKey; DIST_PN: P521CT-ND; I_F: 5; Luminous Intensity: 3; Maximum Continuous Current: 10; V_F: 1.9; Cost (1000): 0.22; Cost (MOQ): 0.33
D2 D4 D6 D8 D10 D12 D14 D18 = LNJ808R8ERA: Orange 0603 5mA 1.8V 1.1mCd; MFG: Panasonic - SSG; DIST: DigiKey; DIST_PN: P523CT-ND; I_F: 5; Luminous Intensity: 1.1; Maximum Continuous Current: 10; V_F: 1.8; Cost (1000): 0.22; Cost (MOQ): 0.33
J21 = H100 3x8 THRU VERT: DIST: Samtec; DIST_PN: TSW-108-07-T-T
J23 = H100 2x4 THRU VERT: 2x4 Bird Pins; DIST: Samtec; DIST_PN: TSW-104-07-T-D; BOM Note: Generic
RP3 RP7 = 10k 5% 4x0603 Isolated: as RP15 on sheet cRIO Connectors
RP4 RP6 RP8 RP10-RP14 = 680 5% 4x0603 Isolated: 680 5% Isolated Resistor Network; MFG: Yageo; MFG_PN: YC164-JR-07680RL; DIST: DigiKey; DIST_PN: YC164J-680CT-ND; Number of Resistors: 4; Power: 62.5mW; Value: 680; Cost (1000): 0.00630; Cost (MOQ): 0.01100
RP5 RP9 = 10K 5% 4x0603 Isolated: as RP19 on sheet cRIO Connectors
U2#2 U3 U4 = SN74LV595ADR Shift Register: 8 bit Shift Register with D Latching; MFG: Texas Instruments; DIST: DigiKey; DIST_PN: 296-18747-1-ND; Checked: SCH 11/17/07; Output Current: 16 mA @ 5 V; Cost (1000): 0.31920; Cost (MOQ): 0.96000

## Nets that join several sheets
5V: cRIO Connectors (33 pins), PWM Outputs (C1.2 C15.2 U2#1.20 U8.8), Power (5 pins), Relay Outputs (10 pins)
6V: PWM Outputs (10 pins), Power (5 pins)
GND: cRIO Connectors (38 pins), PWM Outputs (14 pins), Power (21 pins), Relay Outputs (48 pins)
/Output_EN: cRIO Connectors (J24.25 RP20.1), PWM Outputs (U2#1.1 U2#1.19 U8.1 U8.7), Relay Outputs (U2#2.13 U3.13)
BFL: Power (Q1.G R4.2), Relay Outputs (U4.15)
I2C_SCL: cRIO Connectors (5 pins), Relay Outputs (J23.3)
I2C_SDA: cRIO Connectors (5 pins), Relay Outputs (J23.5)
PWM1: cRIO Connectors (J24.26 RP16.5), PWM Outputs (U2#1.2)
PWM2: cRIO Connectors (J24.27 RP16.1), PWM Outputs (U2#1.17)
PWM3: cRIO Connectors (J24.30 RP21.5), PWM Outputs (U2#1.4)
PWM4: cRIO Connectors (J24.31 RP21.1), PWM Outputs (U2#1.15)
PWM5: cRIO Connectors (J24.32 RP17.5), PWM Outputs (U2#1.6)
PWM6: cRIO Connectors (J24.33 RP17.1), PWM Outputs (U2#1.13)
PWM7: cRIO Connectors (J24.34 RP22.5), PWM Outputs (U2#1.8)
PWM8: cRIO Connectors (J24.35 RP22.1), PWM Outputs (U2#1.11)
PWM9: cRIO Connectors (J24.36 RP18.5), PWM Outputs (U8.2)
PWM10: cRIO Connectors (J24.37 RP18.1), PWM Outputs (U8.5)
Relay_Output_CLK: cRIO Connectors (J24.24 RP20.5), Relay Outputs (U2#2.12 U3.12 U4.12)
Relay_Serial_Data: cRIO Connectors (J24.22 RP15.5), Relay Outputs (U2#2.14)
Relay_Shift_CLK: cRIO Connectors (J24.23 RP15.1), Relay Outputs (U2#2.11 U3.11 U4.11)

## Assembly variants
SideCar with I2C: all parts fitted
SideCar with SPI: not fitted Q3 Q4 R13 R14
